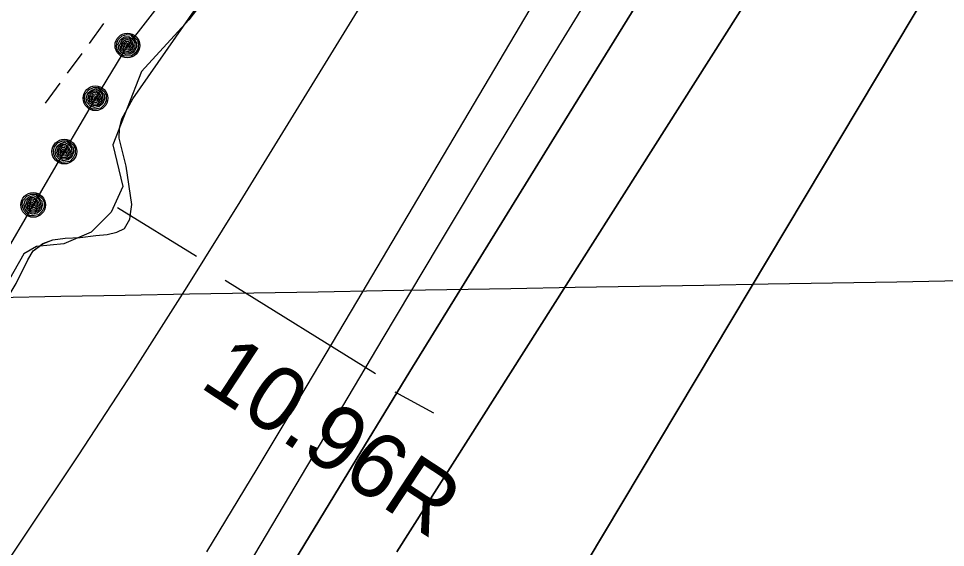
# Model space of a CAD drawing. Extents: x 3905714 to 3926767, y 183354 to 205755.
# Drawn here: x 3915917 to 3916517, y 193245 to 193588 of the extents above; entities that cross this region are included whole.
import ezdxf

# ---------------------------------------------------------------- set-up
doc = ezdxf.new("R2010")
doc.units = 0
for name, color, linetype in [('V-GRID-MAJR', 7, 'Continuous'), ('V-LEVE-TOET', 7, 'Continuous'), ('V-RIVR-EDGE', 7, 'Continuous'), ('V-RRAP-FSHR', 7, 'Continuous'), ('V-STRM-FMON', 7, 'Continuous'), ('V-TOPO-DPTH', 7, 'Continuous'), ('V-TOPO-MINR', 7, 'Continuous'), ('V-TOPO-SHOR', 7, 'Continuous'), ('V-WETL-SWMP', 7, 'Continuous')]:
    doc.layers.add(name, color=color, linetype=linetype)

msp = doc.modelspace()

# ---------------------------------------------------------------- linework, layer by layer
at = {"layer": 'V-GRID-MAJR'}
msp.add_spline([(3911066.23, 193323.42), (3914779.24, 193387.51), (3920105.98, 193480.1), (3922587.21, 193523.5)], degree=3, dxfattribs=at)
at = {"layer": 'V-LEVE-TOET'}
for p, q in [((3916032.18, 193433.35), (3915981.14, 193464.91)), ((3916148.17, 193357.49), (3916050.72, 193417.94)), ((3916185.94, 193331.99), (3916160.74, 193345.44))]:
    msp.add_line(p, q, dxfattribs=at)
at = {"layer": 'V-RIVR-EDGE'}
msp.add_lwpolyline([(3916050.42, 193617.33), (3916027.19, 193586.67), (3915996.53, 193553.21), (3915977.95, 193505.82), (3915984.45, 193478.88), (3915977.02, 193462.15), (3915964.01, 193449.14), (3915946.35, 193441.71), (3915928.7, 193439.85), (3915920.33, 193435.2), (3915845.07, 193302.33)], dxfattribs=at)
at = {"layer": 'V-RRAP-FSHR'}
for points in [[(3916259.73, 193964.8), (3916242.28, 193928.59), (3916220.81, 193894.84), (3916198.92, 193861.37), (3916176.12, 193828.51), (3916153.31, 193795.65), (3916130.5, 193762.79), (3916107.69, 193729.93), (3916084.88, 193697.69), (3916061.18, 193664.99), (3916036.51, 193633.38), (3916011.99, 193601.77), (3915987.48, 193570.16), (3915966.79, 193535.97), (3915946.65, 193501.41), (3915926.51, 193466.85), (3915906.37, 193432.29), (3915886.23, 193397.73), (3915866.31, 193363.43), (3915846.41, 193328.35), (3915826.5, 193293.65), (3915806.52, 193259), (3915786.5, 193224.37)], [(3915990.01, 193577.03), (3915991.72, 193575.85), (3915993.91, 193573.42), (3915994.66, 193570.95), (3915994.23, 193567.76), (3915992.7, 193565.46), (3915990.08, 193563.42), (3915987.18, 193563.31), (3915984.91, 193563.44), (3915982.58, 193565.06), (3915981.09, 193567.1), (3915980.49, 193569.38), (3915980.54, 193571.6), (3915981.53, 193574.02), (3915984.11, 193576.35), (3915987.17, 193577.23), (3915989.56, 193576.97), (3915991.76, 193574.23), (3915993.39, 193571.74), (3915993.26, 193568.96), (3915991.86, 193566.05), (3915989.2, 193564.44), (3915986.19, 193564.37), (3915983.64, 193565.53), (3915981.85, 193568.03), (3915981.56, 193571), (3915983.04, 193574.11), (3915985.69, 193575.76), (3915988.46, 193576.08), (3915991.17, 193574.09), (3915992.29, 193571.56), (3915992.23, 193568.72), (3915990.75, 193566.39), (3915988.37, 193565.23), (3915985.62, 193565.4), (3915983.31, 193567.53), (3915982.54, 193570.27), (3915984.14, 193573.81), (3915986.67, 193575.11), (3915988.56, 193574.93), (3915990.62, 193572.67), (3915991.49, 193569.92), (3915990.61, 193567.64), (3915988.02, 193566.06), (3915985.7, 193566.56), (3915983.62, 193568.84), (3915983.82, 193571.24), (3915985.19, 193573.25), (3915987.11, 193574.24), (3915989.05, 193573.55), (3915989.98, 193571.79), (3915990.46, 193569.54), (3915989.27, 193567.83), (3915987.44, 193567.14), (3915985.42, 193567.96), (3915984.62, 193569.7), (3915984.9, 193571.44), (3915986.5, 193572.98), (3915987.83, 193573.02), (3915989.03, 193571.42), (3915989.33, 193569.52), (3915988.48, 193568.37), (3915986.91, 193568.36), (3915985.49, 193569.58), (3915985.81, 193571.18), (3915986.87, 193571.98), (3915988.24, 193571.07), (3915988.3, 193569.43), (3915987.13, 193569.27), (3915986.57, 193570.26), (3915986.91, 193571.03), (3915987.52, 193570.19)], [(3915968.39, 193543.12), (3915970.24, 193542.17), (3915972.73, 193540.05), (3915973.8, 193537.7), (3915973.79, 193534.48), (3915972.58, 193532.01), (3915970.25, 193529.64), (3915967.39, 193529.14), (3915965.12, 193528.97), (3915962.6, 193530.27), (3915960.85, 193532.1), (3915959.96, 193534.28), (3915959.72, 193536.49), (3915960.38, 193539.02), (3915962.63, 193541.66), (3915965.55, 193542.95), (3915967.95, 193543), (3915970.5, 193540.57), (3915972.44, 193538.32), (3915972.68, 193535.54), (3915971.67, 193532.47), (3915969.25, 193530.53), (3915966.27, 193530.06), (3915963.59, 193530.88), (3915961.48, 193533.12), (3915960.8, 193536.02), (3915961.87, 193539.3), (3915964.27, 193541.28), (3915966.98, 193541.98), (3915969.93, 193540.36), (3915971.37, 193538), (3915971.68, 193535.17), (3915970.53, 193532.66), (3915968.32, 193531.2), (3915965.57, 193531.01), (3915963, 193532.82), (3915961.88, 193535.43), (3915963, 193539.15), (3915965.33, 193540.77), (3915967.23, 193540.84), (3915969.57, 193538.87), (3915970.8, 193536.26), (3915970.23, 193533.89), (3915967.86, 193531.98), (3915965.5, 193532.17), (3915963.14, 193534.16), (3915963.02, 193536.56), (3915964.11, 193538.74), (3915965.88, 193539.97), (3915967.9, 193539.54), (3915969.05, 193537.92), (3915969.82, 193535.75), (3915968.88, 193533.89), (3915967.15, 193532.97), (3915965.04, 193533.52), (3915964.01, 193535.14), (3915964.06, 193536.9), (3915965.44, 193538.64), (3915966.75, 193538.86), (3915968.16, 193537.43), (3915968.71, 193535.58), (3915968.01, 193534.33), (3915966.46, 193534.11), (3915964.89, 193535.13), (3915964.99, 193536.77), (3915965.95, 193537.7), (3915967.42, 193536.98), (3915967.7, 193535.36), (3915966.56, 193535.04), (3915965.87, 193535.95), (3915966.11, 193536.76), (3915966.82, 193536.01)], [(3915948.25, 193508.56), (3915950.1, 193507.61), (3915952.59, 193505.49), (3915953.66, 193503.14), (3915953.65, 193499.92), (3915952.44, 193497.45), (3915950.11, 193495.08), (3915947.25, 193494.58), (3915944.98, 193494.41), (3915942.46, 193495.71), (3915940.71, 193497.54), (3915939.82, 193499.72), (3915939.58, 193501.93), (3915940.24, 193504.46), (3915942.49, 193507.1), (3915945.41, 193508.39), (3915947.81, 193508.44), (3915950.35, 193506.01), (3915952.3, 193503.76), (3915952.54, 193500.98), (3915951.53, 193497.91), (3915949.11, 193495.97), (3915946.13, 193495.5), (3915943.45, 193496.32), (3915941.34, 193498.56), (3915940.66, 193501.46), (3915941.73, 193504.74), (3915944.13, 193506.72), (3915946.84, 193507.42), (3915949.79, 193505.8), (3915951.23, 193503.44), (3915951.54, 193500.61), (3915950.39, 193498.1), (3915948.18, 193496.64), (3915945.43, 193496.45), (3915942.86, 193498.26), (3915941.74, 193500.87), (3915942.86, 193504.59), (3915945.19, 193506.21), (3915947.1, 193506.28), (3915949.43, 193504.31), (3915950.66, 193501.7), (3915950.08, 193499.33), (3915947.72, 193497.42), (3915945.36, 193497.61), (3915943, 193499.6), (3915942.87, 193502.01), (3915943.97, 193504.18), (3915945.74, 193505.41), (3915947.76, 193504.98), (3915948.91, 193503.36), (3915949.68, 193501.19), (3915948.73, 193499.33), (3915947.01, 193498.41), (3915944.9, 193498.96), (3915943.87, 193500.58), (3915943.92, 193502.34), (3915945.3, 193504.08), (3915946.61, 193504.3), (3915948.02, 193502.87), (3915948.57, 193501.02), (3915947.87, 193499.77), (3915946.32, 193499.55), (3915944.75, 193500.57), (3915944.85, 193502.21), (3915945.81, 193503.14), (3915947.28, 193502.42), (3915947.56, 193500.8), (3915946.42, 193500.48), (3915945.73, 193501.39), (3915945.97, 193502.2), (3915946.68, 193501.45)], [(3915928.11, 193474), (3915929.96, 193473.05), (3915932.45, 193470.93), (3915933.52, 193468.58), (3915933.51, 193465.36), (3915932.3, 193462.89), (3915929.97, 193460.52), (3915927.11, 193460.02), (3915924.84, 193459.85), (3915922.32, 193461.15), (3915920.57, 193462.98), (3915919.68, 193465.16), (3915919.44, 193467.37), (3915920.1, 193469.89), (3915922.35, 193472.54), (3915925.27, 193473.83), (3915927.67, 193473.88), (3915930.21, 193471.45), (3915932.16, 193469.2), (3915932.4, 193466.42), (3915931.39, 193463.35), (3915928.97, 193461.41), (3915925.99, 193460.94), (3915923.31, 193461.76), (3915921.2, 193464), (3915920.52, 193466.9), (3915921.58, 193470.18), (3915923.99, 193472.16), (3915926.7, 193472.86), (3915929.65, 193471.24), (3915931.09, 193468.88), (3915931.4, 193466.05), (3915930.25, 193463.54), (3915928.04, 193462.08), (3915925.29, 193461.89), (3915922.72, 193463.7), (3915921.6, 193466.31), (3915922.72, 193470.03), (3915925.05, 193471.65), (3915926.96, 193471.72), (3915929.29, 193469.75), (3915930.52, 193467.14), (3915929.95, 193464.77), (3915927.58, 193462.86), (3915925.22, 193463.05), (3915922.86, 193465.04), (3915922.73, 193467.45), (3915923.83, 193469.62), (3915925.6, 193470.85), (3915927.62, 193470.42), (3915928.77, 193468.8), (3915929.54, 193466.63), (3915928.6, 193464.77), (3915926.87, 193463.85), (3915924.76, 193464.4), (3915923.73, 193466.02), (3915923.78, 193467.79), (3915925.16, 193469.52), (3915926.47, 193469.74), (3915927.88, 193468.31), (3915928.43, 193466.46), (3915927.73, 193465.21), (3915926.18, 193464.99), (3915924.61, 193466.01), (3915924.71, 193467.65), (3915925.67, 193468.58), (3915927.14, 193467.86), (3915927.42, 193466.24), (3915926.28, 193465.92), (3915925.59, 193466.83), (3915925.83, 193467.64), (3915926.54, 193466.89)]]:
    msp.add_lwpolyline(points, dxfattribs=at)
for centre in [(3915987.48, 193570.16), (3915966.79, 193535.97), (3915946.65, 193501.41), (3915926.51, 193466.85)]:
    msp.add_circle(centre, 8, dxfattribs=at)
at = {"layer": 'V-TOPO-DPTH'}
for points in [[(3916225.84, 193136.37), (3916507.9, 193609.29), (3916517.74, 193625.66), (3916527.65, 193641.98), (3916537.69, 193658.22), (3916547.79, 193674.42), (3916677.81, 193881.11), (3916726.25, 193958.01)], [(3916373.89, 193811.54), (3916371.32, 193806.17), (3916362.96, 193789.26), (3916356.59, 193776.68), (3916351.13, 193766.2), (3916345.51, 193755.82), (3916339.64, 193745.58), (3916333.61, 193735.42), (3916313.05, 193701.74), (3916296.68, 193674.78), (3916280.37, 193647.78), (3916264.18, 193620.71), (3916248.05, 193593.6), (3916135.82, 193404.03), (3916103.61, 193349.94), (3916071.24, 193295.95), (3916038.6, 193242.12)], [(3916079.15, 193209.31), (3916124.67, 193284.13), (3916170.32, 193358.88), (3916216.18, 193433.5), (3916262.16, 193508.04), (3916351.34, 193652.17), (3916373, 193687.4), (3916394.53, 193722.7), (3916415.86, 193758.13), (3916424.55, 193772.69)], [(3916424.55, 193772.69), (3916415.86, 193758.13), (3916394.53, 193722.7), (3916373, 193687.4), (3916351.34, 193652.17), (3916262.16, 193508.04), (3916216.18, 193433.5), (3916170.32, 193358.88), (3916124.67, 193284.13), (3916079.15, 193209.31)], [(3916161.87, 193242.13), (3916428.73, 193662.94), (3916437.96, 193677.46), (3916447.21, 193691.97), (3916456.5, 193706.46), (3916465.8, 193720.93), (3916482.27, 193746.49), (3916594.6, 193748.82)], [(3916161.87, 193242.13), (3916428.73, 193662.94), (3916437.96, 193677.46), (3916447.21, 193691.97), (3916456.5, 193706.46), (3916465.8, 193720.93), (3916482.27, 193746.49)], [(3916594.6, 193748.82), (3916547.79, 193674.42), (3916537.69, 193658.22), (3916527.65, 193641.98), (3916517.74, 193625.66), (3916507.9, 193609.29), (3916225.84, 193136.37)]]:
    msp.add_lwpolyline(points, dxfattribs=at)
at = {"layer": 'V-TOPO-MINR'}
for points in [[(3916726.25, 193958.01), (3916677.81, 193881.11), (3916547.79, 193674.42), (3916537.69, 193658.22), (3916527.65, 193641.98), (3916517.74, 193625.66), (3916507.9, 193609.29), (3916225.84, 193136.37)], [(3916302.39, 193862.02), (3916291.68, 193845.05), (3916280.12, 193826.48), (3916268.58, 193807.89), (3916257.09, 193789.28), (3916245.62, 193770.65), (3916060.21, 193468.76), (3916025.95, 193413.77), (3915991.21, 193359.08), (3915955.78, 193304.84), (3915919.87, 193250.9), (3915888.75, 193204.81), (3915867.92, 193174.24), (3915846.9, 193143.8), (3915825.61, 193113.55), (3915804.14, 193083.42), (3915621.99, 192830.25), (3915621.99, 192830.25)], [(3916373.89, 193811.54), (3916371.32, 193806.17), (3916362.96, 193789.26), (3916356.59, 193776.68), (3916351.13, 193766.2), (3916345.51, 193755.82), (3916339.64, 193745.58), (3916333.61, 193735.42), (3916313.05, 193701.74), (3916296.68, 193674.78), (3916280.37, 193647.78), (3916264.18, 193620.71), (3916248.05, 193593.6), (3916135.82, 193404.03), (3916103.61, 193349.94), (3916071.24, 193295.95), (3916038.6, 193242.12)], [(3916399.02, 193790.32), (3916396.32, 193785.47), (3916383.21, 193762.34), (3916369.91, 193739.33), (3916356.33, 193716.48), (3916342.56, 193693.74), (3916297.21, 193619.88), (3916260.77, 193560.22), (3916224.51, 193500.43), (3916188.55, 193440.48), (3916152.77, 193380.41), (3915975.7, 193081.51)], [(3916424.55, 193772.69), (3916415.86, 193758.13), (3916394.53, 193722.7), (3916373, 193687.4), (3916351.34, 193652.17), (3916262.16, 193508.04), (3916216.18, 193433.5), (3916170.32, 193358.88), (3916124.67, 193284.13), (3916079.15, 193209.31)], [(3916482.27, 193746.49), (3916465.8, 193720.93), (3916456.5, 193706.46), (3916447.21, 193691.97), (3916437.96, 193677.46), (3916428.73, 193662.94), (3916161.87, 193242.13)]]:
    msp.add_lwpolyline(points, dxfattribs=at)
at = {"layer": 'V-TOPO-SHOR'}
for points in [[(3915974.41, 193447.67), (3915980.58, 193449.11), (3915985.53, 193451.55), (3915989.02, 193457.7), (3915989.53, 193461.15), (3915990.31, 193467.07), (3915986.75, 193492), (3915982.17, 193510.04), (3915982.46, 193516.45), (3915983.97, 193522.61), (3915990.96, 193535.64), (3916053.65, 193625.56)], [(3915789.38, 193193.18), (3915830.76, 193266.94), (3915886.61, 193367.76), (3915915.51, 193415.94), (3915923, 193431.19), (3915926.49, 193437.1), (3915932.68, 193441.75), (3915939.11, 193444.18), (3915947.26, 193445.36), (3915956.88, 193445.8), (3915967, 193446.97), (3915974.41, 193447.67)]]:
    msp.add_lwpolyline(points, dxfattribs=at)
at = {"layer": 'V-WETL-SWMP'}
for p, q in [((3915990.96, 193535.64), (3916053.65, 193625.56)), ((3915972.1, 193584.4), (3915962.64, 193571.49)), ((3915957.92, 193565.04), (3915948.46, 193552.13)), ((3915943.73, 193545.68), (3915934.28, 193532.77)), ((3915983.97, 193522.61), (3915990.96, 193535.64)), ((3915982.46, 193516.45), (3915983.97, 193522.61)), ((3915982.17, 193510.04), (3915982.46, 193516.45)), ((3915986.75, 193492), (3915982.17, 193510.04)), ((3915990.31, 193467.06), (3915986.75, 193492)), ((3915989.53, 193461.15), (3915990.31, 193467.06)), ((3915985.53, 193451.55), (3915989.02, 193457.7)), ((3915989.02, 193457.7), (3915989.53, 193461.15)), ((3915980.58, 193449.11), (3915985.53, 193451.55)), ((3915939.11, 193444.17), (3915947.26, 193445.36)), ((3915947.26, 193445.36), (3915956.88, 193445.8)), ((3915956.88, 193445.8), (3915967, 193446.97)), ((3915967, 193446.97), (3915974.41, 193447.67)), ((3915974.41, 193447.67), (3915980.58, 193449.11)), ((3915926.49, 193437.09), (3915932.68, 193441.74)), ((3915932.68, 193441.74), (3915939.11, 193444.17)), ((3915923, 193431.19), (3915926.49, 193437.09)), ((3915915.51, 193415.94), (3915923, 193431.19))]:
    msp.add_line(p, q, dxfattribs=at)

# ---------------------------------------------------------------- texts
at = {"layer": 'V-STRM-FMON'}
msp.add_text('10.96R', height=42, rotation=326.66461, dxfattribs=at).set_placement((3916033.37, 193349.39))

doc.saveas('drawing.dxf')
